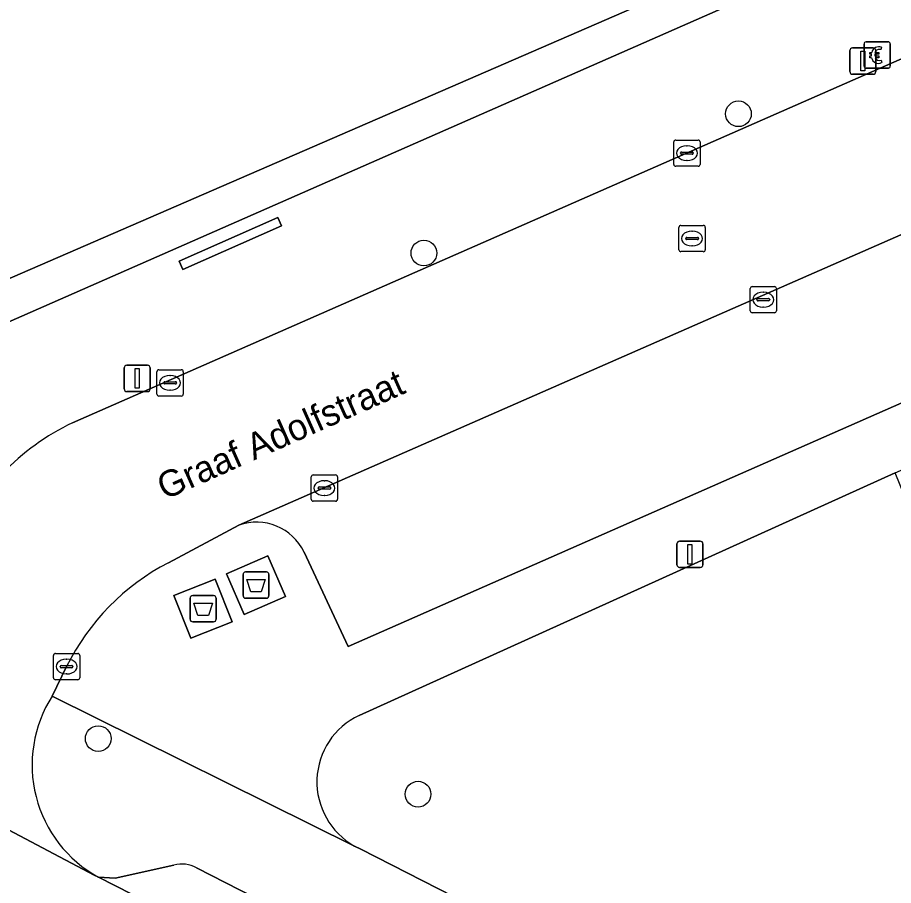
# Model space of a CAD drawing. Extents: x 159960 to 160866, y 382700 to 383354.
# Drawn here: x 160231.45 to 160264.81, y 382964.93 to 382997.98 of the extents above; entities that cross this region are included whole.
import ezdxf

# ---------------------------------------------------------------- set-up
doc = ezdxf.new("R2010")
doc.units = 0
for name, color, linetype in [('IMGEO_Afval_apart_plaats', 7, 'Continuous'), ('IMGEO_Betaalautomaat', 7, 'Continuous'), ('IMGEO_Boom', 7, 'Continuous'), ('IMGEO_Erf', 7, 'Continuous'), ('IMGEO_Groenvoorziening', 7, 'Continuous'), ('IMGEO_Kolk', 7, 'Continuous'), ('IMGEO_Lichtmast', 7, 'Continuous'), ('IMGEO_Openbare_ruimte_label', 7, 'Continuous'), ('IMGEO_Pand', 7, 'Continuous'), ('IMGEO_Parkeervlak_open', 7, 'Continuous'), ('IMGEO_Rijbaan_lokaal_open', 7, 'Continuous'), ('IMGEO_Rioolput', 7, 'Continuous'), ('IMGEO_Voetpad_gesloten', 7, 'Continuous'), ('IMGEO_Voetpad_open', 7, 'Continuous')]:
    doc.layers.add(name, color=color, linetype=linetype)

msp = doc.modelspace()

# ---------------------------------------------------------------- linework, layer by layer
at = {"layer": 'IMGEO_Afval_apart_plaats'}
for p, q in [((160240.137, 382976.872), (160240.927, 382976.872)), ((160240.927, 382976.872), (160240.137, 382976.872)), ((160240.037, 382975.972), (160240.037, 382976.772)), ((160240.037, 382976.772), (160240.037, 382975.972)), ((160241.027, 382976.772), (160241.027, 382975.972)), ((160241.027, 382975.972), (160241.027, 382976.772)), ((160238.023, 382975.073), (160238.023, 382975.873)), ((160238.023, 382975.873), (160238.023, 382975.073)), ((160238.123, 382975.973), (160238.913, 382975.973)), ((160238.913, 382975.973), (160238.123, 382975.973)), ((160239.013, 382975.873), (160239.013, 382975.073)), ((160239.013, 382975.073), (160239.013, 382975.873)), ((160240.927, 382975.872), (160240.137, 382975.872)), ((160240.137, 382975.872), (160240.927, 382975.872)), ((160238.913, 382974.973), (160238.123, 382974.973)), ((160238.123, 382974.973), (160238.913, 382974.973))]:
    msp.add_line(p, q, dxfattribs=at)
for points in [[(160240.18, 382976.586), (160240.884, 382976.586), (160240.735, 382976.116), (160240.329, 382976.116), (160240.18, 382976.586)], [(160238.166, 382975.687), (160238.87, 382975.687), (160238.721, 382975.217), (160238.315, 382975.217), (160238.166, 382975.687)]]:
    msp.add_lwpolyline(points, dxfattribs=at)
for centre, start, end in [((160240.137, 382976.772), 90, 180), ((160240.137, 382976.772), 90, 180), ((160240.927, 382976.772), 0, 90), ((160240.927, 382976.772), 360, 90), ((160238.123, 382975.873), 90, 180), ((160238.123, 382975.873), 90, 180), ((160238.913, 382975.873), 0, 90), ((160238.913, 382975.873), 360, 90), ((160240.137, 382975.972), 180, 270), ((160240.137, 382975.972), 180, 270), ((160240.927, 382975.972), 270, 0), ((160240.927, 382975.972), 270, 0), ((160238.123, 382975.073), 180, 270), ((160238.123, 382975.073), 180, 270), ((160238.913, 382975.073), 270, 0), ((160238.913, 382975.073), 270, 0)]:
    msp.add_arc(centre, 0.1, start, end, dxfattribs=at)
at = {"layer": 'IMGEO_Betaalautomaat'}
for p, q in [((160263.691, 382996.131), (160263.691, 382996.972)), ((160263.691, 382996.972), (160263.691, 382996.131)), ((160263.766, 382997.055), (160264.607, 382997.055)), ((160264.607, 382997.055), (160263.766, 382997.055)), ((160264.353, 382996.86), (160264.336, 382996.76)), ((160264.69, 382996.981), (160264.69, 382996.14)), ((160264.69, 382996.14), (160264.69, 382996.981)), ((160263.974, 382996.519), (160263.974, 382996.587)), ((160264.095, 382996.587), (160264.095, 382996.519)), ((160264.34, 382996.354), (160264.362, 382996.267)), ((160264.616, 382996.056), (160263.775, 382996.056)), ((160263.775, 382996.056), (160264.616, 382996.056))]:
    msp.add_line(p, q, dxfattribs=at)
for points in [[(160263.974, 382996.587), (160263.905, 382996.587), (160263.905, 382996.656), (160263.984, 382996.656)], [(160263.979, 382996.45), (160263.905, 382996.45), (160263.905, 382996.519), (160263.974, 382996.519)], [(160264.106, 382996.656), (160264.253, 382996.656), (160264.253, 382996.587), (160264.095, 382996.587)], [(160264.095, 382996.519), (160264.253, 382996.519), (160264.253, 382996.45), (160264.109, 382996.45)]]:
    msp.add_lwpolyline(points, dxfattribs=at)
for centre, radius, start, end in [((160263.769, 382996.978), 0.0779, 92.4484, 184.2845), ((160263.769, 382996.978), 0.0779, 92.4484, 184.2845), ((160264.267, 382996.58), 0.293, 73.014, 165.0139), ((160264.613, 382996.978), 0.0779, 2.4484, 94.2845), ((160264.613, 382996.978), 0.0779, 2.4484, 94.2845), ((160264.273, 382996.593), 0.179, 69.3236, 159.5683), ((160264.24, 382996.505), 0.267, 191.8096, 297.0389), ((160264.273, 382996.52), 0.179, 202.7625, 291.8693), ((160263.769, 382996.134), 0.0779, 182.4484, 274.2845), ((160263.769, 382996.134), 0.0779, 182.4484, 274.2845), ((160264.613, 382996.134), 0.0779, 272.4484, 4.2845), ((160264.613, 382996.134), 0.0779, 272.4484, 4.2845)]:
    msp.add_arc(centre, radius, start, end, dxfattribs=at)
at = {"layer": 'IMGEO_Boom'}
for centre in [(160258.907, 382994.319), (160246.925, 382989.015), (160234.522, 382970.525), (160246.703, 382968.411)]:
    msp.add_circle(centre, 0.489, dxfattribs=at)
at = {"layer": 'IMGEO_Erf'}
for points in [[(160297.308, 383016.984), (160258.674, 383000), (160226.74, 382986.142), (160227.406, 382984.773), (160297.863, 383015.722)], [(160241.509, 382990.052), (160241.367, 382990.373), (160237.601, 382988.709), (160237.743, 382988.388)]]:
    msp.add_lwpolyline(points, close=True, dxfattribs=at)
at = {"layer": 'IMGEO_Groenvoorziening'}
for points in [[(160317.027, 382970.5), (160319.505, 382975.412), (160316.003, 382983.683), (160314.265, 382984.46), (160271.091, 382965.33), (160264.871, 382980.644), (160244.464, 382971.411)], [(160244.285, 382966.435), (160244.529, 382966.314), (160274.502, 382951.013), (160346.467, 382914.274), (160346.839, 382914.085)]]:
    msp.add_lwpolyline(points, dxfattribs=at)
msp.add_arc((160245.648, 382968.877), 2.797, 115.045, 240.8347, dxfattribs=at)
at = {"layer": 'IMGEO_Kolk'}
for p, q in [((160256.445, 382992.393), (160256.445, 382993.245)), ((160256.52, 382993.319), (160257.372, 382993.319)), ((160257.446, 382993.245), (160257.446, 382992.393)), ((160256.704, 382992.813), (160256.704, 382992.825)), ((160256.747, 382992.862), (160257.145, 382992.862)), ((160256.933, 382993.099), (160256.958, 382993.099)), ((160257.188, 382992.825), (160257.188, 382992.813)), ((160257.142, 382992.776), (160256.744, 382992.776)), ((160256.956, 382992.539), (160256.931, 382992.539)), ((160257.372, 382992.319), (160256.52, 382992.319)), ((160259.354, 382986.814), (160259.354, 382987.666)), ((160259.429, 382987.74), (160260.281, 382987.74)), ((160259.842, 382987.52), (160259.867, 382987.52)), ((160260.355, 382987.666), (160260.355, 382986.814)), ((160259.613, 382987.234), (160259.613, 382987.246)), ((160260.051, 382987.197), (160259.653, 382987.197)), ((160259.656, 382987.283), (160260.054, 382987.283)), ((160260.097, 382987.246), (160260.097, 382987.234)), ((160259.865, 382986.96), (160259.84, 382986.96)), ((160260.281, 382986.74), (160259.429, 382986.74)), ((160236.76, 382983.646), (160236.76, 382984.498)), ((160236.835, 382984.572), (160237.687, 382984.572)), ((160237.761, 382984.498), (160237.761, 382983.646)), ((160237.248, 382984.352), (160237.273, 382984.352)), ((160237.019, 382984.066), (160237.019, 382984.078)), ((160237.457, 382984.029), (160237.059, 382984.029)), ((160237.062, 382984.115), (160237.46, 382984.115)), ((160237.503, 382984.078), (160237.503, 382984.066)), ((160237.687, 382983.572), (160236.835, 382983.572)), ((160237.271, 382983.792), (160237.246, 382983.792)), ((160242.637, 382979.64), (160242.637, 382980.492)), ((160242.712, 382980.566), (160243.564, 382980.566)), ((160243.638, 382980.492), (160243.638, 382979.64)), ((160243.125, 382980.346), (160243.15, 382980.346)), ((160242.896, 382980.06), (160242.896, 382980.072)), ((160243.334, 382980.023), (160242.936, 382980.023)), ((160242.939, 382980.109), (160243.337, 382980.109)), ((160243.38, 382980.072), (160243.38, 382980.06)), ((160243.564, 382979.566), (160242.712, 382979.566)), ((160243.148, 382979.786), (160243.123, 382979.786)), ((160232.818, 382972.843), (160232.818, 382973.695)), ((160232.893, 382973.769), (160233.745, 382973.769)), ((160233.306, 382973.549), (160233.331, 382973.549)), ((160233.819, 382973.695), (160233.819, 382972.843)), ((160233.077, 382973.263), (160233.077, 382973.275)), ((160233.515, 382973.226), (160233.117, 382973.226)), ((160233.12, 382973.312), (160233.518, 382973.312)), ((160233.561, 382973.275), (160233.561, 382973.263)), ((160233.329, 382972.989), (160233.304, 382972.989)), ((160233.745, 382972.769), (160232.893, 382972.769))]:
    msp.add_line(p, q, dxfattribs=at)
for points in [[(160256.445, 382992.393), (160256.445, 382993.245)], [(160256.52, 382993.319), (160257.372, 382993.319)], [(160257.446, 382993.245), (160257.446, 382992.393)], [(160257.372, 382992.319), (160256.52, 382992.319)], [(160259.354, 382986.814), (160259.354, 382987.666)], [(160259.429, 382987.74), (160260.281, 382987.74)], [(160260.355, 382987.666), (160260.355, 382986.814)], [(160260.281, 382986.74), (160259.429, 382986.74)], [(160236.76, 382983.646), (160236.76, 382984.498)], [(160236.835, 382984.572), (160237.687, 382984.572)], [(160237.761, 382984.498), (160237.761, 382983.646)], [(160237.687, 382983.572), (160236.835, 382983.572)], [(160242.637, 382979.64), (160242.637, 382980.492)], [(160242.712, 382980.566), (160243.564, 382980.566)], [(160243.638, 382980.492), (160243.638, 382979.64)], [(160243.564, 382979.566), (160242.712, 382979.566)], [(160232.818, 382972.843), (160232.818, 382973.695)], [(160232.893, 382973.769), (160233.745, 382973.769)], [(160233.819, 382973.695), (160233.819, 382972.843)], [(160233.745, 382972.769), (160232.893, 382972.769)]]:
    msp.add_lwpolyline(points, dxfattribs=at)
for centre, radius, start, end in [((160256.522, 382993.243), 0.0765, 91.552, 178.448), ((160256.522, 382993.243), 0.0765, 91.552, 178.448), ((160257.37, 382993.243), 0.0765, 1.552, 88.448), ((160257.37, 382993.243), 0.0765, 1.552, 88.448), ((160256.744, 382992.822), 0.0403, 85.8775, 175.7526), ((160256.741, 382992.812), 0.0366, 178.938, 274.7102), ((160257.145, 382992.819), 0.043, 264.8664, 352.4533), ((160257.149, 382992.824), 0.0386, 1.7309, 96.639), ((160256.522, 382992.395), 0.0765, 181.552, 268.448), ((160256.522, 382992.395), 0.0765, 181.552, 268.448), ((160257.37, 382992.395), 0.0765, 271.552, 358.448), ((160257.37, 382992.395), 0.0765, 271.552, 358.448), ((160259.431, 382987.664), 0.0765, 91.552, 178.448), ((160259.431, 382987.664), 0.0765, 91.552, 178.448), ((160260.279, 382987.664), 0.0765, 1.552, 88.448), ((160260.279, 382987.664), 0.0765, 1.552, 88.448), ((160259.653, 382987.243), 0.0403, 85.8775, 175.7526), ((160259.65, 382987.233), 0.0366, 178.938, 274.7102), ((160260.054, 382987.24), 0.043, 264.8664, 352.4533), ((160260.058, 382987.245), 0.0386, 1.7309, 96.639), ((160259.431, 382986.816), 0.0765, 181.552, 268.448), ((160259.431, 382986.816), 0.0765, 181.552, 268.448), ((160260.279, 382986.816), 0.0765, 271.552, 358.448), ((160260.279, 382986.816), 0.0765, 271.552, 358.448), ((160236.837, 382984.496), 0.0765, 91.552, 178.448), ((160236.837, 382984.496), 0.0765, 91.552, 178.448), ((160237.685, 382984.496), 0.0765, 1.552, 88.448), ((160237.685, 382984.496), 0.0765, 1.552, 88.448), ((160237.059, 382984.075), 0.0403, 85.8775, 175.7526), ((160237.056, 382984.065), 0.0366, 178.938, 274.7102), ((160237.46, 382984.072), 0.043, 264.8664, 352.4533), ((160237.464, 382984.077), 0.0386, 1.7309, 96.639), ((160236.837, 382983.648), 0.0765, 181.552, 268.448), ((160236.837, 382983.648), 0.0765, 181.552, 268.448), ((160237.685, 382983.648), 0.0765, 271.552, 358.448), ((160237.685, 382983.648), 0.0765, 271.552, 358.448), ((160242.714, 382980.49), 0.0765, 91.552, 178.448), ((160242.714, 382980.49), 0.0765, 91.552, 178.448), ((160243.562, 382980.49), 0.0765, 1.552, 88.448), ((160243.562, 382980.49), 0.0765, 1.552, 88.448), ((160242.936, 382980.069), 0.0403, 85.8775, 175.7526), ((160242.933, 382980.059), 0.0366, 178.938, 274.7102), ((160243.337, 382980.066), 0.043, 264.8664, 352.4533), ((160243.341, 382980.071), 0.0386, 1.7309, 96.639), ((160242.714, 382979.642), 0.0765, 181.552, 268.448), ((160242.714, 382979.642), 0.0765, 181.552, 268.448), ((160243.562, 382979.642), 0.0765, 271.552, 358.448), ((160243.562, 382979.642), 0.0765, 271.552, 358.448), ((160232.895, 382973.693), 0.0765, 91.552, 178.448), ((160232.895, 382973.693), 0.0765, 91.552, 178.448), ((160233.743, 382973.693), 0.0765, 1.552, 88.448), ((160233.743, 382973.693), 0.0765, 1.552, 88.448), ((160233.117, 382973.272), 0.0403, 85.8775, 175.7526), ((160233.114, 382973.262), 0.0366, 178.938, 274.7102), ((160233.518, 382973.269), 0.043, 264.8664, 352.4533), ((160233.522, 382973.274), 0.0386, 1.7309, 96.639), ((160232.895, 382972.845), 0.0765, 181.552, 268.448), ((160232.895, 382972.845), 0.0765, 181.552, 268.448), ((160233.743, 382972.845), 0.0765, 271.552, 358.448), ((160233.743, 382972.845), 0.0765, 271.552, 358.448)]:
    msp.add_arc(centre, radius, start, end, dxfattribs=at)
for centre, major_axis, ratio, start_param, end_param in [((160256.932, 382992.819), (-0.387, 0.002), 0.722429, 4.712389, 7.853982), ((160256.957, 382992.819), (-0.39, 0.002), 0.717154, 1.570796, 4.712389), ((160259.841, 382987.24), (-0.387, 0.002), 0.722429, 4.712389, 7.853982), ((160259.866, 382987.24), (-0.39, 0.002), 0.717154, 1.570796, 4.712389), ((160237.247, 382984.072), (-0.387, 0.002), 0.722429, 4.712389, 7.853982), ((160237.272, 382984.072), (-0.39, 0.002), 0.717154, 1.570796, 4.712389), ((160243.124, 382980.066), (-0.387, 0.002), 0.722429, 4.712389, 7.853982), ((160243.149, 382980.066), (-0.39, 0.002), 0.717154, 1.570796, 4.712389), ((160233.305, 382973.269), (-0.387, 0.002), 0.722429, 4.712389, 7.853982), ((160233.33, 382973.269), (-0.39, 0.002), 0.717154, 1.570796, 4.712389)]:
    msp.add_ellipse(centre, major_axis=major_axis, ratio=ratio, start_param=start_param, end_param=end_param, dxfattribs=at)
at = {"layer": 'IMGEO_Lichtmast'}
for p, q in [((160263.25, 382996.824), (160264.04, 382996.824)), ((160264.04, 382996.824), (160263.25, 382996.824)), ((160263.15, 382995.924), (160263.15, 382996.724)), ((160263.15, 382996.724), (160263.15, 382995.924)), ((160264.14, 382996.724), (160264.14, 382995.924)), ((160264.14, 382995.924), (160264.14, 382996.724)), ((160264.04, 382995.824), (160263.25, 382995.824)), ((160263.25, 382995.824), (160264.04, 382995.824)), ((160235.511, 382983.841), (160235.511, 382984.641)), ((160235.511, 382984.641), (160235.511, 382983.841)), ((160235.611, 382984.741), (160236.401, 382984.741)), ((160236.401, 382984.741), (160235.611, 382984.741)), ((160236.501, 382984.641), (160236.501, 382983.841)), ((160236.501, 382983.841), (160236.501, 382984.641)), ((160236.401, 382983.741), (160235.611, 382983.741)), ((160235.611, 382983.741), (160236.401, 382983.741)), ((160256.564, 382977.146), (160256.564, 382977.946)), ((160256.564, 382977.946), (160256.564, 382977.146)), ((160256.664, 382978.046), (160257.454, 382978.046)), ((160257.454, 382978.046), (160256.664, 382978.046)), ((160257.554, 382977.946), (160257.554, 382977.146)), ((160257.554, 382977.146), (160257.554, 382977.946)), ((160257.454, 382977.046), (160256.664, 382977.046)), ((160256.664, 382977.046), (160257.454, 382977.046))]:
    msp.add_line(p, q, dxfattribs=at)
for points in [[(160263.57, 382996.699), (160263.72, 382996.699), (160263.72, 382995.949), (160263.57, 382995.949), (160263.57, 382996.699)], [(160235.931, 382984.616), (160236.081, 382984.616), (160236.081, 382983.866), (160235.931, 382983.866), (160235.931, 382984.616)], [(160256.984, 382977.921), (160257.134, 382977.921), (160257.134, 382977.171), (160256.984, 382977.171), (160256.984, 382977.921)]]:
    msp.add_lwpolyline(points, dxfattribs=at)
for centre, start, end in [((160263.25, 382996.724), 90, 180), ((160263.25, 382996.724), 90, 180), ((160264.04, 382996.724), 0, 90), ((160264.04, 382996.724), 360, 90), ((160263.25, 382995.924), 180, 270), ((160263.25, 382995.924), 180, 270), ((160264.04, 382995.924), 270, 0), ((160264.04, 382995.924), 270, 0), ((160235.611, 382984.641), 90, 180), ((160235.611, 382984.641), 90, 180), ((160236.401, 382984.641), 0, 90), ((160236.401, 382984.641), 360, 90), ((160235.611, 382983.841), 180, 270), ((160235.611, 382983.841), 180, 270), ((160236.401, 382983.841), 270, 0), ((160236.401, 382983.841), 270, 0), ((160256.664, 382977.946), 90, 180), ((160256.664, 382977.946), 90, 180), ((160257.454, 382977.946), 0, 90), ((160257.454, 382977.946), 360, 90), ((160256.664, 382977.146), 180, 270), ((160256.664, 382977.146), 180, 270), ((160257.454, 382977.146), 270, 0), ((160257.454, 382977.146), 270, 0)]:
    msp.add_arc(centre, 0.1, start, end, dxfattribs=at)
at = {"layer": 'IMGEO_Pand'}
msp.add_lwpolyline([(160226.74, 382986.142), (160258.674, 383000), (160297.308, 383016.984), (160292.649, 383027.642), (160229.378, 383000), (160222.051, 382996.799)], close=True, dxfattribs=at)
at = {"layer": 'IMGEO_Parkeervlak_open'}
for points in [[(160299.303, 383004.724), (160239.877, 382978.654)], [(160242.363, 382977.624), (160244.047, 382974.036), (160300.097, 382998.703), (160299.561, 383000), (160298.648, 383002.211)], [(160237.406, 382965.704), (160235.172, 382965.213), (160234.53, 382965.25), (160277.799, 382943.195), (160278.689, 382944.938), (160272.983, 382947.855), (160238.269, 382965.603)]]:
    msp.add_lwpolyline(points, dxfattribs=at)
for centre, radius, start, end in [((160240.551, 382976.765), 2.005, 25.3587, 109.6309), ((160237.721, 382964.658), 1.092, 59.8883, 106.7614)]:
    msp.add_arc(centre, radius, start, end, dxfattribs=at)
at = {"layer": 'IMGEO_Rijbaan_lokaal_open'}
for points in [[(160294.224, 383009.205), (160233.543, 382982.549)], [(160237.194, 382977.222), (160239.877, 382978.654), (160299.303, 383004.724), (160300.29, 383005.626)], [(160232.768, 382972.147), (160233.319, 382973.269)], [(160221.466, 382972.141), (160234.37, 382965.333), (160234.53, 382965.25)]]:
    msp.add_lwpolyline(points, dxfattribs=at)
msp.add_lwpolyline([(160276.427, 382940.509), (160276.427, 382940.509), (160277.799, 382943.195), (160234.53, 382965.25), (160234.37, 382965.333), (160221.466, 382972.141), (160213.891, 382975.973), (160206.512, 382980.099), (160206.182, 382980.31), (160204.4, 382977.293)], close=True, dxfattribs=at)
for centre, radius, start, end in [((160237.509, 382974.252), 9.197, 115.5474, 156.6608), ((160241.267, 382969.353), 8.86, 117.3687, 153.7731), ((160236.882, 382969.524), 4.879, 147.4846, 241.1774)]:
    msp.add_arc(centre, radius, start, end, dxfattribs=at)
at = {"layer": 'IMGEO_Rioolput'}
for p, q in [((160256.642, 382989.142), (160256.642, 382989.994)), ((160256.717, 382990.068), (160257.569, 382990.068)), ((160257.13, 382989.848), (160257.155, 382989.848)), ((160257.643, 382989.994), (160257.643, 382989.142)), ((160256.901, 382989.562), (160256.901, 382989.574)), ((160257.339, 382989.525), (160256.941, 382989.525)), ((160256.944, 382989.611), (160257.342, 382989.611)), ((160257.385, 382989.574), (160257.385, 382989.562)), ((160257.153, 382989.288), (160257.128, 382989.288)), ((160257.569, 382989.068), (160256.717, 382989.068))]:
    msp.add_line(p, q, dxfattribs=at)
for points in [[(160256.642, 382989.142), (160256.642, 382989.994)], [(160256.717, 382990.068), (160257.569, 382990.068)], [(160257.643, 382989.994), (160257.643, 382989.142)], [(160257.569, 382989.068), (160256.717, 382989.068)]]:
    msp.add_lwpolyline(points, dxfattribs=at)
for centre, radius, start, end in [((160256.719, 382989.992), 0.0765, 91.552, 178.448), ((160256.719, 382989.992), 0.0765, 91.552, 178.448), ((160257.567, 382989.992), 0.0765, 1.552, 88.448), ((160257.567, 382989.992), 0.0765, 1.552, 88.448), ((160256.941, 382989.571), 0.0403, 85.8775, 175.7526), ((160256.938, 382989.561), 0.0366, 178.938, 274.7102), ((160257.342, 382989.568), 0.043, 264.8664, 352.4533), ((160257.346, 382989.573), 0.0386, 1.7309, 96.639), ((160256.719, 382989.144), 0.0765, 181.552, 268.448), ((160256.719, 382989.144), 0.0765, 181.552, 268.448), ((160257.567, 382989.144), 0.0765, 271.552, 358.448), ((160257.567, 382989.144), 0.0765, 271.552, 358.448)]:
    msp.add_arc(centre, radius, start, end, dxfattribs=at)
for centre, major_axis, ratio, start_param, end_param in [((160257.129, 382989.568), (-0.387, 0.002), 0.722429, 4.712389, 7.853982), ((160257.154, 382989.568), (-0.39, 0.002), 0.717154, 1.570796, 4.712389)]:
    msp.add_ellipse(centre, major_axis=major_axis, ratio=ratio, start_param=start_param, end_param=end_param, dxfattribs=at)
at = {"layer": 'IMGEO_Voetpad_gesloten'}
for points in [[(160240.987, 382977.485), (160239.41, 382976.805), (160240.077, 382975.258), (160241.654, 382975.938)], [(160238.98, 382976.6), (160237.407, 382975.972), (160238.056, 382974.346), (160239.629, 382974.974)]]:
    msp.add_lwpolyline(points, close=True, dxfattribs=at)
at = {"layer": 'IMGEO_Voetpad_open'}
for points in [[(160291.641, 383030.493), (160292.175, 383028.72), (160292.649, 383027.642), (160297.308, 383016.984), (160297.863, 383015.722), (160227.406, 382984.773), (160218.256, 382980.741)], [(160233.543, 382982.549), (160294.224, 383009.205)], [(160244.464, 382971.411), (160264.871, 382980.644), (160268.268, 382982.137), (160296.207, 382994.388), (160308.936, 383000), (160310.309, 383000.605), (160312.699, 383001.659), (160312.984, 383001.767)], [(160302.643, 382999.819), (160300.097, 382998.703), (160244.047, 382974.036), (160242.363, 382977.624)], [(160239.877, 382978.654), (160237.194, 382977.222)], [(160233.319, 382973.269), (160232.768, 382972.147), (160244.285, 382966.435)], [(160274.502, 382951.013), (160244.529, 382966.314), (160244.285, 382966.435), (160232.768, 382972.147)], [(160234.53, 382965.25), (160235.172, 382965.213), (160237.406, 382965.704)], [(160238.269, 382965.603), (160272.983, 382947.855), (160278.689, 382944.938), (160283.096, 382942.668), (160341.004, 382913.133)]]:
    msp.add_lwpolyline(points, dxfattribs=at)
for points in [[(160241.509, 382990.052), (160237.743, 382988.388), (160237.601, 382988.709), (160241.367, 382990.373)], [(160240.077, 382975.258), (160239.41, 382976.805), (160240.987, 382977.485), (160241.654, 382975.938)], [(160238.056, 382974.346), (160237.407, 382975.972), (160238.98, 382976.6), (160239.629, 382974.974)]]:
    msp.add_lwpolyline(points, close=True, dxfattribs=at)
for centre, radius, start, end in [((160237.509, 382974.252), 9.197, 115.5474, 156.6608), ((160240.551, 382976.765), 2.005, 25.3587, 109.6309), ((160241.267, 382969.353), 8.86, 117.3687, 153.7731), ((160236.882, 382969.524), 4.879, 147.4846, 241.1774), ((160245.648, 382968.877), 2.797, 115.045, 240.8347), ((160237.721, 382964.658), 1.092, 59.8883, 106.7614)]:
    msp.add_arc(centre, radius, start, end, dxfattribs=at)

# ---------------------------------------------------------------- texts
at = {"layer": 'IMGEO_Openbare_ruimte_label'}
msp.add_text('Graaf Adolfstraat', height=1, rotation=23.9509, dxfattribs=at).set_placement((160237.05, 382979.604))

doc.saveas('drawing.dxf')
